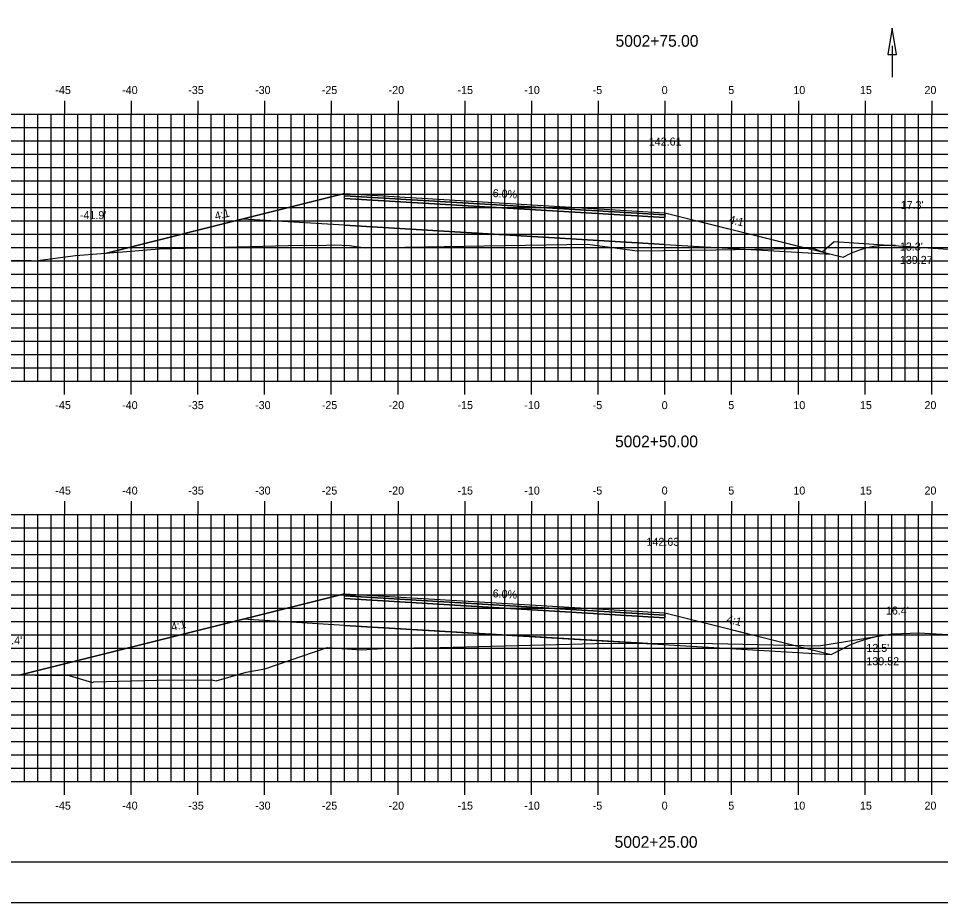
# Model space of a CAD drawing. Extents: x 851417 to 851588, y 365876 to 365986.
# Drawn here: x 851451.5 to 851520.6, y 365875.8 to 365942 of the extents above; entities that cross this region are included whole.
import ezdxf

# ---------------------------------------------------------------- set-up
doc = ezdxf.new("R2010")
doc.units = 0
for name, color, linetype in [('ANNOTATION', 7, 'Continuous'), ('BORDER', 7, 'Continuous'), ('D_Drainage_Ditch_Line', 7, 'Continuous'), ('D_Roadway_Centerline', 7, 'Continuous'), ('D_Roadway_Centerline_Text', 7, 'Continuous'), ('D_Roadway_Edge_TW', 7, 'Continuous'), ('D_Roadway_FinishedGrade', 7, 'Continuous'), ('D_Roadway_Pavement', 7, 'Continuous'), ('D_Roadway_SlopeLines', 7, 'Continuous'), ('D_Roadway_SubGrade', 7, 'Continuous'), ('D_Text_Standard', 7, 'Continuous'), ('H_V ANNOTATION', 7, 'Continuous'), ('MAJOR', 7, 'Continuous'), ('MINOR', 7, 'Continuous'), ('PLOT BOUNDARY', 7, 'Continuous'), ('S_Roadway_Centerline', 7, 'Continuous')]:
    doc.layers.add(name, color=color, linetype=linetype)

msp = doc.modelspace()

# ---------------------------------------------------------------- linework, layer by layer
at = {"layer": 'BORDER'}
msp.add_lwpolyline([(851424.899, 365878.833), (851584.899, 365878.833), (851584.899, 365983.833), (851424.899, 365983.833)], close=True, dxfattribs=at)
at = {"layer": 'D_Drainage_Ditch_Line'}
msp.add_line((851516.923, 365939.952), (851516.923, 365937.603), dxfattribs=at)
msp.add_lwpolyline([(851516.595, 365939.296), (851517.251, 365939.296), (851516.923, 365941.264)], close=True, dxfattribs=at)
at = {"layer": 'D_Roadway_Centerline'}
for points in [[(851458.043, 365924.417), (851465.898, 365926.381), (851475.898, 365928.881), (851499.898, 365927.441), (851509.898, 365924.941), (851510.521, 365924.785)], [(851451.512, 365892.806), (851465.898, 365896.402), (851475.898, 365898.902), (851499.898, 365897.462), (851509.558, 365895.047)]]:
    msp.add_lwpolyline(points, dxfattribs=at)
at = {"layer": 'D_Roadway_Edge_TW'}
for points in [[(851475.898, 365928.881), (851499.898, 365927.441), (851499.898, 365927.274), (851475.898, 365928.714)], [(851475.898, 365898.902), (851499.898, 365897.462), (851499.898, 365897.296), (851475.898, 365898.736)]]:
    msp.add_lwpolyline(points, close=True, dxfattribs=at)
at = {"layer": 'D_Roadway_FinishedGrade'}
for p, q in [((851475.898, 365926.514), (851468.264, 365926.972)), ((851475.898, 365926.514), (851499.898, 365925.074)), ((851499.898, 365925.074), (851512.355, 365924.327)), ((851513.248, 365924.103), (851513.558, 365924.259)), ((851475.898, 365896.536), (851468.264, 365896.994)), ((851512.355, 365894.348), (851513.362, 365894.852))]:
    msp.add_line(p, q, dxfattribs=at)
msp.add_lwpolyline([(851499.898, 365895.096), (851475.898, 365896.536), (851512.355, 365894.348)], dxfattribs=at)
for centre, radius, start in [((851516.689, 365917.998), 7, 86.07913), ((851517.834, 365885.908), 10, 99.11489)]:
    msp.add_arc(centre, radius, start, 116.56505, dxfattribs=at)
at = {"layer": 'D_Roadway_Pavement'}
for points in [[(851475.898, 365928.714), (851499.898, 365927.274), (851499.898, 365927.074), (851475.898, 365928.514)], [(851475.898, 365898.736), (851499.898, 365897.296), (851499.898, 365897.096), (851475.898, 365898.536)]]:
    msp.add_lwpolyline(points, close=True, dxfattribs=at)
for points in [[(851499.898, 365927.274), (851499.898, 365927.074)], [(851499.898, 365927.274), (851499.898, 365927.074)], [(851499.898, 365897.296), (851499.898, 365897.096)], [(851499.898, 365897.296), (851499.898, 365897.096)]]:
    msp.add_lwpolyline(points, dxfattribs=at)
at = {"layer": 'D_Roadway_SlopeLines'}
for points in [[(851475.898, 365928.881), (851465.898, 365926.381), (851458.043, 365924.417)], [(851499.898, 365927.441), (851513.248, 365924.103)], [(851475.898, 365898.902), (851465.898, 365896.402), (851451.512, 365892.806)], [(851499.898, 365897.462), (851512.355, 365894.348)]]:
    msp.add_lwpolyline(points, dxfattribs=at)
at = {"layer": 'D_Roadway_SubGrade'}
for points in [[(851475.898, 365928.514), (851499.898, 365927.074)], [(851499.898, 365925.074), (851475.898, 365926.514)], [(851475.898, 365898.536), (851499.898, 365897.096)], [(851499.898, 365895.096), (851475.898, 365896.536)]]:
    msp.add_lwpolyline(points, dxfattribs=at)
at = {"layer": 'MAJOR'}
for p, q in [((851454.898, 365935.835), (851454.898, 365934.833)), ((851459.898, 365935.835), (851459.898, 365934.833)), ((851464.898, 365935.835), (851464.898, 365934.833)), ((851469.898, 365935.835), (851469.898, 365934.833)), ((851474.898, 365935.835), (851474.898, 365934.833)), ((851479.898, 365935.835), (851479.898, 365934.833)), ((851484.898, 365935.835), (851484.898, 365934.833)), ((851489.898, 365935.835), (851489.898, 365934.833)), ((851494.898, 365935.835), (851494.898, 365934.833)), ((851499.898, 365935.835), (851499.898, 365934.833)), ((851504.898, 365935.835), (851504.898, 365934.833)), ((851509.898, 365935.835), (851509.898, 365934.833)), ((851514.898, 365935.835), (851514.898, 365934.833)), ((851519.898, 365935.835), (851519.898, 365934.833)), ((851429.898, 365934.833), (851569.898, 365934.833)), ((851429.898, 365934.833), (851569.898, 365934.833)), ((851454.898, 365914.833), (851454.898, 365934.833)), ((851459.898, 365914.833), (851459.898, 365934.833)), ((851464.898, 365914.833), (851464.898, 365934.833)), ((851469.898, 365914.833), (851469.898, 365934.833)), ((851474.898, 365914.833), (851474.898, 365934.833)), ((851479.898, 365914.833), (851479.898, 365934.833)), ((851484.898, 365914.833), (851484.898, 365934.833)), ((851489.898, 365914.833), (851489.898, 365934.833)), ((851494.898, 365914.833), (851494.898, 365934.833)), ((851499.898, 365914.833), (851499.898, 365934.833)), ((851504.898, 365914.833), (851504.898, 365934.833)), ((851509.898, 365914.833), (851509.898, 365934.833)), ((851514.898, 365914.833), (851514.898, 365934.833)), ((851519.898, 365914.833), (851519.898, 365934.833)), ((851429.898, 365929.833), (851569.898, 365929.833)), ((851429.898, 365924.833), (851569.898, 365924.833)), ((851429.898, 365919.833), (851569.898, 365919.833)), ((851429.898, 365914.833), (851569.898, 365914.833)), ((851429.898, 365914.833), (851569.898, 365914.833)), ((851454.898, 365913.831), (851454.898, 365914.833)), ((851459.898, 365913.831), (851459.898, 365914.833)), ((851464.898, 365913.831), (851464.898, 365914.833)), ((851469.898, 365913.831), (851469.898, 365914.833)), ((851474.898, 365913.831), (851474.898, 365914.833)), ((851479.898, 365913.831), (851479.898, 365914.833)), ((851484.898, 365913.831), (851484.898, 365914.833)), ((851489.898, 365913.831), (851489.898, 365914.833)), ((851494.898, 365913.831), (851494.898, 365914.833)), ((851499.898, 365913.831), (851499.898, 365914.833)), ((851504.898, 365913.831), (851504.898, 365914.833)), ((851509.898, 365913.831), (851509.898, 365914.833)), ((851514.898, 365913.831), (851514.898, 365914.833)), ((851519.898, 365913.831), (851519.898, 365914.833)), ((851454.898, 365905.835), (851454.898, 365904.833)), ((851459.898, 365905.835), (851459.898, 365904.833)), ((851464.898, 365905.835), (851464.898, 365904.833)), ((851469.898, 365905.835), (851469.898, 365904.833)), ((851474.898, 365905.835), (851474.898, 365904.833)), ((851479.898, 365905.835), (851479.898, 365904.833)), ((851484.898, 365905.835), (851484.898, 365904.833)), ((851489.898, 365905.835), (851489.898, 365904.833)), ((851494.898, 365905.835), (851494.898, 365904.833)), ((851499.898, 365905.835), (851499.898, 365904.833)), ((851504.898, 365905.835), (851504.898, 365904.833)), ((851509.898, 365905.835), (851509.898, 365904.833)), ((851514.898, 365905.835), (851514.898, 365904.833)), ((851519.898, 365905.835), (851519.898, 365904.833)), ((851429.898, 365904.833), (851569.898, 365904.833)), ((851429.898, 365904.833), (851569.898, 365904.833)), ((851454.898, 365884.833), (851454.898, 365904.833)), ((851459.898, 365884.833), (851459.898, 365904.833)), ((851464.898, 365884.833), (851464.898, 365904.833)), ((851469.898, 365884.833), (851469.898, 365904.833)), ((851474.898, 365884.833), (851474.898, 365904.833)), ((851479.898, 365884.833), (851479.898, 365904.833)), ((851484.898, 365884.833), (851484.898, 365904.833)), ((851489.898, 365884.833), (851489.898, 365904.833)), ((851494.898, 365884.833), (851494.898, 365904.833)), ((851499.898, 365884.833), (851499.898, 365904.833)), ((851504.898, 365884.833), (851504.898, 365904.833)), ((851509.898, 365884.833), (851509.898, 365904.833)), ((851514.898, 365884.833), (851514.898, 365904.833)), ((851519.898, 365884.833), (851519.898, 365904.833)), ((851429.898, 365899.833), (851569.898, 365899.833)), ((851429.898, 365894.833), (851569.898, 365894.833)), ((851429.898, 365889.833), (851569.898, 365889.833)), ((851429.898, 365884.833), (851569.898, 365884.833)), ((851429.898, 365884.833), (851569.898, 365884.833)), ((851454.898, 365883.831), (851454.898, 365884.833)), ((851459.898, 365883.831), (851459.898, 365884.833)), ((851464.898, 365883.831), (851464.898, 365884.833)), ((851469.898, 365883.831), (851469.898, 365884.833)), ((851474.898, 365883.831), (851474.898, 365884.833)), ((851479.898, 365883.831), (851479.898, 365884.833)), ((851484.898, 365883.831), (851484.898, 365884.833)), ((851489.898, 365883.831), (851489.898, 365884.833)), ((851494.898, 365883.831), (851494.898, 365884.833)), ((851499.898, 365883.831), (851499.898, 365884.833)), ((851504.898, 365883.831), (851504.898, 365884.833)), ((851509.898, 365883.831), (851509.898, 365884.833)), ((851514.898, 365883.831), (851514.898, 365884.833)), ((851519.898, 365883.831), (851519.898, 365884.833))]:
    msp.add_line(p, q, dxfattribs=at)
at = {"layer": 'MINOR'}
for p, q in [((851451.898, 365914.833), (851451.898, 365934.833)), ((851452.898, 365914.833), (851452.898, 365934.833)), ((851453.898, 365914.833), (851453.898, 365934.833)), ((851455.898, 365914.833), (851455.898, 365934.833)), ((851456.898, 365914.833), (851456.898, 365934.833)), ((851457.898, 365914.833), (851457.898, 365934.833)), ((851458.898, 365914.833), (851458.898, 365934.833)), ((851460.898, 365914.833), (851460.898, 365934.833)), ((851461.898, 365914.833), (851461.898, 365934.833)), ((851462.898, 365914.833), (851462.898, 365934.833)), ((851463.898, 365914.833), (851463.898, 365934.833)), ((851465.898, 365914.833), (851465.898, 365934.833)), ((851466.898, 365914.833), (851466.898, 365934.833)), ((851467.898, 365914.833), (851467.898, 365934.833)), ((851468.898, 365914.833), (851468.898, 365934.833)), ((851470.898, 365914.833), (851470.898, 365934.833)), ((851471.898, 365914.833), (851471.898, 365934.833)), ((851472.898, 365914.833), (851472.898, 365934.833)), ((851473.898, 365914.833), (851473.898, 365934.833)), ((851475.898, 365914.833), (851475.898, 365934.833)), ((851476.898, 365914.833), (851476.898, 365934.833)), ((851477.898, 365914.833), (851477.898, 365934.833)), ((851478.898, 365914.833), (851478.898, 365934.833)), ((851480.898, 365914.833), (851480.898, 365934.833)), ((851481.898, 365914.833), (851481.898, 365934.833)), ((851482.898, 365914.833), (851482.898, 365934.833)), ((851483.898, 365914.833), (851483.898, 365934.833)), ((851485.898, 365914.833), (851485.898, 365934.833)), ((851486.898, 365914.833), (851486.898, 365934.833)), ((851487.898, 365914.833), (851487.898, 365934.833)), ((851488.898, 365914.833), (851488.898, 365934.833)), ((851490.898, 365914.833), (851490.898, 365934.833)), ((851491.898, 365914.833), (851491.898, 365934.833)), ((851492.898, 365914.833), (851492.898, 365934.833)), ((851493.898, 365914.833), (851493.898, 365934.833)), ((851495.898, 365914.833), (851495.898, 365934.833)), ((851496.898, 365914.833), (851496.898, 365934.833)), ((851497.898, 365914.833), (851497.898, 365934.833)), ((851498.898, 365914.833), (851498.898, 365934.833)), ((851500.898, 365914.833), (851500.898, 365934.833)), ((851501.898, 365914.833), (851501.898, 365934.833)), ((851502.898, 365914.833), (851502.898, 365934.833)), ((851503.898, 365914.833), (851503.898, 365934.833)), ((851505.898, 365914.833), (851505.898, 365934.833)), ((851506.898, 365914.833), (851506.898, 365934.833)), ((851507.898, 365914.833), (851507.898, 365934.833)), ((851508.898, 365914.833), (851508.898, 365934.833)), ((851510.898, 365914.833), (851510.898, 365934.833)), ((851511.898, 365914.833), (851511.898, 365934.833)), ((851512.898, 365914.833), (851512.898, 365934.833)), ((851513.898, 365914.833), (851513.898, 365934.833)), ((851515.898, 365914.833), (851515.898, 365934.833)), ((851516.898, 365914.833), (851516.898, 365934.833)), ((851517.898, 365914.833), (851517.898, 365934.833)), ((851518.898, 365914.833), (851518.898, 365934.833)), ((851429.898, 365933.833), (851569.898, 365933.833)), ((851429.898, 365932.833), (851569.898, 365932.833)), ((851429.898, 365931.833), (851569.898, 365931.833)), ((851429.898, 365930.833), (851569.898, 365930.833)), ((851429.898, 365928.833), (851569.898, 365928.833)), ((851429.898, 365927.833), (851569.898, 365927.833)), ((851429.898, 365926.833), (851569.898, 365926.833)), ((851429.898, 365925.833), (851569.898, 365925.833)), ((851429.898, 365923.833), (851569.898, 365923.833)), ((851429.898, 365922.833), (851569.898, 365922.833)), ((851429.898, 365921.833), (851569.898, 365921.833)), ((851429.898, 365920.833), (851569.898, 365920.833)), ((851429.898, 365918.833), (851569.898, 365918.833)), ((851429.898, 365917.833), (851569.898, 365917.833)), ((851429.898, 365916.833), (851569.898, 365916.833)), ((851429.898, 365915.833), (851569.898, 365915.833)), ((851451.898, 365884.833), (851451.898, 365904.833)), ((851452.898, 365884.833), (851452.898, 365904.833)), ((851453.898, 365884.833), (851453.898, 365904.833)), ((851455.898, 365884.833), (851455.898, 365904.833)), ((851456.898, 365884.833), (851456.898, 365904.833)), ((851457.898, 365884.833), (851457.898, 365904.833)), ((851458.898, 365884.833), (851458.898, 365904.833)), ((851460.898, 365884.833), (851460.898, 365904.833)), ((851461.898, 365884.833), (851461.898, 365904.833)), ((851462.898, 365884.833), (851462.898, 365904.833)), ((851463.898, 365884.833), (851463.898, 365904.833)), ((851465.898, 365884.833), (851465.898, 365904.833)), ((851466.898, 365884.833), (851466.898, 365904.833)), ((851467.898, 365884.833), (851467.898, 365904.833)), ((851468.898, 365884.833), (851468.898, 365904.833)), ((851470.898, 365884.833), (851470.898, 365904.833)), ((851471.898, 365884.833), (851471.898, 365904.833)), ((851472.898, 365884.833), (851472.898, 365904.833)), ((851473.898, 365884.833), (851473.898, 365904.833)), ((851475.898, 365884.833), (851475.898, 365904.833)), ((851476.898, 365884.833), (851476.898, 365904.833)), ((851477.898, 365884.833), (851477.898, 365904.833)), ((851478.898, 365884.833), (851478.898, 365904.833)), ((851480.898, 365884.833), (851480.898, 365904.833)), ((851481.898, 365884.833), (851481.898, 365904.833)), ((851482.898, 365884.833), (851482.898, 365904.833)), ((851483.898, 365884.833), (851483.898, 365904.833)), ((851485.898, 365884.833), (851485.898, 365904.833)), ((851486.898, 365884.833), (851486.898, 365904.833)), ((851487.898, 365884.833), (851487.898, 365904.833)), ((851488.898, 365884.833), (851488.898, 365904.833)), ((851490.898, 365884.833), (851490.898, 365904.833)), ((851491.898, 365884.833), (851491.898, 365904.833)), ((851492.898, 365884.833), (851492.898, 365904.833)), ((851493.898, 365884.833), (851493.898, 365904.833)), ((851495.898, 365884.833), (851495.898, 365904.833)), ((851496.898, 365884.833), (851496.898, 365904.833)), ((851497.898, 365884.833), (851497.898, 365904.833)), ((851498.898, 365884.833), (851498.898, 365904.833)), ((851500.898, 365884.833), (851500.898, 365904.833)), ((851501.898, 365884.833), (851501.898, 365904.833)), ((851502.898, 365884.833), (851502.898, 365904.833)), ((851503.898, 365884.833), (851503.898, 365904.833)), ((851505.898, 365884.833), (851505.898, 365904.833)), ((851506.898, 365884.833), (851506.898, 365904.833)), ((851507.898, 365884.833), (851507.898, 365904.833)), ((851508.898, 365884.833), (851508.898, 365904.833)), ((851510.898, 365884.833), (851510.898, 365904.833)), ((851511.898, 365884.833), (851511.898, 365904.833)), ((851512.898, 365884.833), (851512.898, 365904.833)), ((851513.898, 365884.833), (851513.898, 365904.833)), ((851515.898, 365884.833), (851515.898, 365904.833)), ((851516.898, 365884.833), (851516.898, 365904.833)), ((851517.898, 365884.833), (851517.898, 365904.833)), ((851518.898, 365884.833), (851518.898, 365904.833)), ((851429.898, 365903.833), (851569.898, 365903.833)), ((851429.898, 365902.833), (851569.898, 365902.833)), ((851429.898, 365901.833), (851569.898, 365901.833)), ((851429.898, 365900.833), (851569.898, 365900.833)), ((851429.898, 365898.833), (851569.898, 365898.833)), ((851429.898, 365897.833), (851569.898, 365897.833)), ((851429.898, 365896.833), (851569.898, 365896.833)), ((851429.898, 365895.833), (851569.898, 365895.833)), ((851429.898, 365893.833), (851569.898, 365893.833)), ((851429.898, 365892.833), (851569.898, 365892.833)), ((851429.898, 365891.833), (851569.898, 365891.833)), ((851429.898, 365890.833), (851569.898, 365890.833)), ((851429.898, 365888.833), (851569.898, 365888.833)), ((851429.898, 365887.833), (851569.898, 365887.833)), ((851429.898, 365886.833), (851569.898, 365886.833)), ((851429.898, 365885.833), (851569.898, 365885.833))]:
    msp.add_line(p, q, dxfattribs=at)
at = {"layer": 'PLOT BOUNDARY'}
msp.add_lwpolyline([(851416.805, 365875.774), (851586.805, 365875.774), (851586.805, 365985.774), (851416.805, 365985.774)], close=True, dxfattribs=at)
at = {"layer": 'S_Roadway_Centerline'}
for points in [[(851450.942, 365923.866), (851452.19, 365923.878), (851452.711, 365923.836), (851455.716, 365924.232), (851459.245, 365924.512), (851461.991, 365924.74), (851472.664, 365925.011), (851473.912, 365924.99), (851475.124, 365925.039), (851476.254, 365924.993), (851477.438, 365924.821), (851486.346, 365924.971), (851494.102, 365925.081), (851497.828, 365924.577), (851503.708, 365924.657), (851511.013, 365924.794), (851511.671, 365924.51), (851512.576, 365925.296), (851522.222, 365924.635)], [(851450.071, 365892.818), (851455.254, 365892.773), (851457.007, 365892.248), (851457.1, 365892.311), (851461.789, 365892.422), (851465.938, 365892.462), (851466.276, 365892.376), (851468.524, 365893.023), (851469.91, 365893.291), (851474.585, 365894.875), (851477.164, 365894.711), (851479.116, 365894.823), (851483.065, 365894.887), (851495.645, 365895.194), (851503.459, 365895.166), (851511.446, 365895.011), (851516.948, 365895.893), (851518.942, 365895.978), (851526.681, 365895.522)]]:
    msp.add_lwpolyline(points, dxfattribs=at)

# ---------------------------------------------------------------- texts
at = {"layer": 'ANNOTATION'}
for s, rotation, p in [('6.0%', 356.56637, (851486.976, 365928.618)), ('4:1', 14.03624, (851466.239, 365926.896)), ('4:1', 345.96376, (851504.651, 365926.683)), ('6.0%', 356.56637, (851486.976, 365898.64)), ('4:1', 345.96376, (851504.481, 365896.747)), ('4:1', 14.03624, (851462.973, 365896.102))]:
    msp.add_text(s, height=0.6, rotation=rotation, dxfattribs=at).set_placement(p)
at = {"layer": 'D_Roadway_Centerline_Text'}
for s, p in [('142.61', (851498.689, 365932.473)), ('142.63', (851498.515, 365902.494))]:
    msp.add_text(s, height=0.6, dxfattribs=at).set_placement(p)
at = {"layer": 'D_Text_Standard'}
for s, p in [("17.3'", (851517.569, 365927.723)), ("-41.9'", (851456.055, 365926.966)), ("13.3' ", (851517.509, 365924.608)), ('139.27', (851517.509, 365923.608)), ("16.4'", (851516.461, 365897.346)), ("-48.4'", (851449.747, 365895.114)), ("12.5' ", (851514.996, 365894.548)), ('139.52', (851514.996, 365893.548))]:
    msp.add_text(s, height=0.6, dxfattribs=at).set_placement(p)
at = {"layer": 'H_V ANNOTATION'}
for s, height, p in [('5002+75.00', 0.875, (851496.199, 365939.876)), ('-45', 0.6, (851454.216, 365936.333)), ('-40', 0.6, (851459.224, 365936.333)), ('-35', 0.6, (851464.179, 365936.333)), ('-30', 0.6, (851469.187, 365936.333)), ('-25', 0.6, (851474.184, 365936.333)), ('-20', 0.6, (851479.192, 365936.333)), ('-15', 0.6, (851484.355, 365936.333)), ('-10', 0.6, (851489.363, 365936.333)), ('-5', 0.6, (851494.489, 365936.333)), ('0', 0.6, (851499.657, 365936.333)), ('5', 0.6, (851504.649, 365936.333)), ('10', 0.6, (851509.524, 365936.333)), ('15', 0.6, (851514.516, 365936.333)), ('20', 0.6, (851519.352, 365936.333)), ('-45', 0.6, (851454.216, 365912.733)), ('-40', 0.6, (851459.224, 365912.733)), ('-35', 0.6, (851464.179, 365912.733)), ('-30', 0.6, (851469.187, 365912.733)), ('-25', 0.6, (851474.184, 365912.733)), ('-20', 0.6, (851479.192, 365912.733)), ('-15', 0.6, (851484.355, 365912.733)), ('-10', 0.6, (851489.363, 365912.733)), ('-5', 0.6, (851494.489, 365912.733)), ('0', 0.6, (851499.657, 365912.733)), ('5', 0.6, (851504.649, 365912.733)), ('10', 0.6, (851509.524, 365912.733)), ('15', 0.6, (851514.516, 365912.733)), ('20', 0.6, (851519.352, 365912.733)), ('5002+50.00', 0.875, (851496.16, 365909.876)), ('-45', 0.6, (851454.216, 365906.333)), ('-40', 0.6, (851459.224, 365906.333)), ('-35', 0.6, (851464.179, 365906.333)), ('-30', 0.6, (851469.187, 365906.333)), ('-25', 0.6, (851474.184, 365906.333)), ('-20', 0.6, (851479.192, 365906.333)), ('-15', 0.6, (851484.355, 365906.333)), ('-10', 0.6, (851489.363, 365906.333)), ('-5', 0.6, (851494.489, 365906.333)), ('0', 0.6, (851499.657, 365906.333)), ('5', 0.6, (851504.649, 365906.333)), ('10', 0.6, (851509.524, 365906.333)), ('15', 0.6, (851514.516, 365906.333)), ('20', 0.6, (851519.352, 365906.333)), ('-45', 0.6, (851454.216, 365882.733)), ('-40', 0.6, (851459.224, 365882.733)), ('-35', 0.6, (851464.179, 365882.733)), ('-30', 0.6, (851469.187, 365882.733)), ('-25', 0.6, (851474.184, 365882.733)), ('-20', 0.6, (851479.192, 365882.733)), ('-15', 0.6, (851484.355, 365882.733)), ('-10', 0.6, (851489.363, 365882.733)), ('-5', 0.6, (851494.489, 365882.733)), ('0', 0.6, (851499.657, 365882.733)), ('5', 0.6, (851504.649, 365882.733)), ('10', 0.6, (851509.524, 365882.733)), ('15', 0.6, (851514.516, 365882.733)), ('20', 0.6, (851519.352, 365882.733)), ('5002+25.00', 0.875, (851496.129, 365879.876))]:
    msp.add_text(s, height=height, dxfattribs=at).set_placement(p)

doc.saveas('drawing.dxf')
